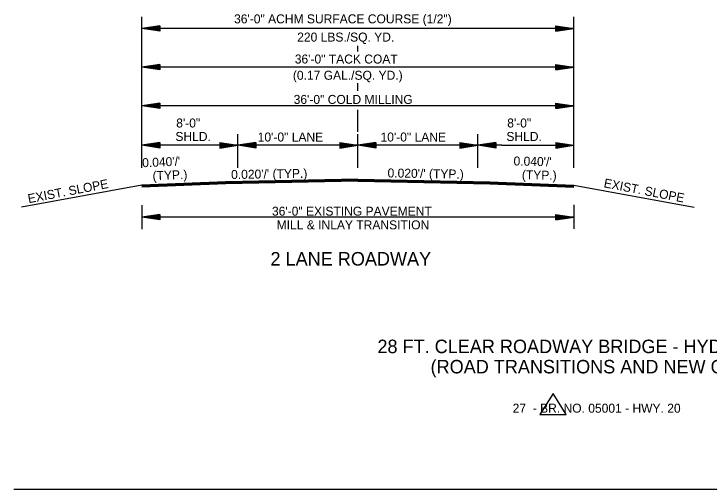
# Model space of a CAD drawing. Extents: x 544199 to 1930787, y -1968972 to 596640.
# Drawn here: x 546303 to 546882, y -1960808 to -1960412 of the extents above; entities that cross this region are included whole.
import ezdxf

# ---------------------------------------------------------------- set-up
doc = ezdxf.new("R2010")
doc.units = 0
doc.layers.add('R_Border', color=7, linetype='Continuous')
doc.layers.add('R_Draft', color=7, linetype='Continuous')

msp = doc.modelspace()

# ---------------------------------------------------------------- linework, layer by layer
at = {"layer": 'R_Border'}
for p, q in [((546479.58, -1960552.03), (546409.58, -1960554.83)), ((546479.58, -1960552.33), (546409.58, -1960555.13)), ((546479.58, -1960552.63), (546409.58, -1960555.43)), ((546479.58, -1960552.93), (546409.58, -1960555.73)), ((546479.58, -1960553.23), (546409.58, -1960556.03)), ((546479.58, -1960553.53), (546409.58, -1960556.33)), ((546479.58, -1960553.7), (546409.58, -1960556.5)), ((546699.58, -1960552.03), (546769.58, -1960554.83)), ((546699.58, -1960552.33), (546769.58, -1960555.13)), ((546699.58, -1960552.63), (546769.58, -1960555.43)), ((546699.58, -1960552.93), (546769.58, -1960555.73)), ((546699.58, -1960553.23), (546769.58, -1960556.03)), ((546699.58, -1960553.53), (546769.58, -1960556.33)), ((546699.58, -1960553.7), (546769.58, -1960556.5)), ((546752.16, -1960728.48), (546741.12, -1960745.79)), ((546763.21, -1960745.79), (546752.16, -1960728.48)), ((546741.12, -1960745.79), (546763.21, -1960745.79)), ((546303.14, -1960808.08), (547224.71, -1960808.08))]:
    msp.add_line(p, q, dxfattribs=at)
at = {"layer": 'R_Draft'}
for p, q in [((546409.58, -1960540.28), (546409.58, -1960414.32)), ((546769.58, -1960540.28), (546769.58, -1960414.32)), ((546424.58, -1960421.96), (546409.58, -1960424.21)), ((546424.58, -1960422.34), (546412.08, -1960424.21)), ((546424.58, -1960422.72), (546414.66, -1960424.21)), ((546424.58, -1960423.09), (546417.16, -1960424.21)), ((546424.58, -1960423.48), (546419.7, -1960424.21)), ((546424.58, -1960421.96), (546424.58, -1960426.46)), ((546754.58, -1960421.96), (546769.58, -1960424.21)), ((546754.58, -1960426.46), (546754.58, -1960421.96)), ((546754.58, -1960422.34), (546767.07, -1960424.21)), ((546754.58, -1960422.72), (546764.49, -1960424.21)), ((546754.58, -1960423.09), (546762, -1960424.21)), ((546754.58, -1960423.48), (546759.45, -1960424.21)), ((546769.58, -1960424.21), (546409.58, -1960424.21)), ((546424.58, -1960426.46), (546409.58, -1960424.21)), ((546424.58, -1960426.09), (546412.08, -1960424.21)), ((546424.58, -1960425.7), (546414.66, -1960424.21)), ((546424.58, -1960425.33), (546417.16, -1960424.21)), ((546424.58, -1960424.95), (546419.7, -1960424.21)), ((546424.58, -1960423.86), (546422.21, -1960424.21)), ((546424.58, -1960424.56), (546422.21, -1960424.21)), ((546754.58, -1960423.86), (546756.95, -1960424.21)), ((546754.58, -1960426.46), (546769.58, -1960424.21)), ((546754.58, -1960424.94), (546759.45, -1960424.21)), ((546754.58, -1960425.7), (546764.49, -1960424.21)), ((546754.58, -1960426.09), (546767.07, -1960424.21)), ((546754.58, -1960425.33), (546762, -1960424.21)), ((546754.58, -1960424.56), (546756.95, -1960424.21)), ((546589.58, -1960443.18), (546589.58, -1960438.56)), ((546424.58, -1960454.05), (546409.58, -1960456.3)), ((546769.58, -1960456.3), (546409.58, -1960456.3)), ((546424.58, -1960458.55), (546409.58, -1960456.3)), ((546424.58, -1960454.42), (546412.08, -1960456.3)), ((546424.58, -1960458.17), (546412.08, -1960456.3)), ((546424.58, -1960454.8), (546414.66, -1960456.3)), ((546424.58, -1960457.79), (546414.66, -1960456.3)), ((546424.58, -1960455.18), (546417.16, -1960456.3)), ((546424.58, -1960457.41), (546417.16, -1960456.3)), ((546424.58, -1960455.57), (546419.7, -1960456.3)), ((546424.58, -1960457.03), (546419.7, -1960456.3)), ((546424.58, -1960455.94), (546422.21, -1960456.3)), ((546424.58, -1960456.65), (546422.21, -1960456.3)), ((546424.58, -1960454.05), (546424.58, -1960458.55)), ((546754.58, -1960454.05), (546769.58, -1960456.3)), ((546754.58, -1960458.55), (546754.58, -1960454.05)), ((546754.58, -1960454.42), (546767.07, -1960456.3)), ((546754.58, -1960454.8), (546764.49, -1960456.3)), ((546754.58, -1960455.18), (546762, -1960456.3)), ((546754.58, -1960455.56), (546759.45, -1960456.3)), ((546754.58, -1960455.94), (546756.95, -1960456.3)), ((546754.58, -1960458.55), (546769.58, -1960456.3)), ((546754.58, -1960457.02), (546759.45, -1960456.3)), ((546754.58, -1960457.79), (546764.49, -1960456.3)), ((546754.58, -1960458.17), (546767.07, -1960456.3)), ((546754.58, -1960457.41), (546762, -1960456.3)), ((546754.58, -1960456.65), (546756.95, -1960456.3)), ((546589.58, -1960475.99), (546589.58, -1960469.83)), ((546424.58, -1960486.43), (546409.58, -1960488.68)), ((546424.58, -1960486.81), (546412.08, -1960488.68)), ((546424.58, -1960487.19), (546414.66, -1960488.68)), ((546424.58, -1960486.43), (546424.58, -1960490.93)), ((546754.58, -1960486.43), (546769.58, -1960488.68)), ((546754.58, -1960490.93), (546754.58, -1960486.43)), ((546754.58, -1960486.81), (546767.07, -1960488.68)), ((546754.58, -1960487.19), (546764.49, -1960488.68)), ((546769.58, -1960488.68), (546409.58, -1960488.68)), ((546424.58, -1960490.93), (546409.58, -1960488.68)), ((546424.58, -1960490.56), (546412.08, -1960488.68)), ((546424.58, -1960490.17), (546414.66, -1960488.68)), ((546424.58, -1960487.56), (546417.16, -1960488.68)), ((546424.58, -1960489.8), (546417.16, -1960488.68)), ((546424.58, -1960487.95), (546419.7, -1960488.68)), ((546424.58, -1960489.42), (546419.7, -1960488.68)), ((546424.58, -1960488.33), (546422.21, -1960488.68)), ((546424.58, -1960489.03), (546422.21, -1960488.68)), ((546589.58, -1960500.33), (546589.58, -1960492.06)), ((546754.58, -1960487.56), (546762, -1960488.68)), ((546754.58, -1960487.95), (546759.45, -1960488.68)), ((546754.58, -1960488.33), (546756.95, -1960488.68)), ((546754.58, -1960490.93), (546769.58, -1960488.68)), ((546754.58, -1960489.41), (546759.45, -1960488.68)), ((546754.58, -1960490.17), (546764.49, -1960488.68)), ((546754.58, -1960490.56), (546767.07, -1960488.68)), ((546754.58, -1960489.8), (546762, -1960488.68)), ((546754.58, -1960489.03), (546756.95, -1960488.68)), ((546589.58, -1960510.2), (546589.58, -1960500.33)), ((546489.58, -1960540.28), (546489.58, -1960512.33)), ((546589.58, -1960540.28), (546589.58, -1960512.33)), ((546689.58, -1960540.28), (546689.58, -1960512.33)), ((546424.58, -1960519.27), (546409.58, -1960521.52)), ((546469.58, -1960521.52), (546409.58, -1960521.52)), ((546424.58, -1960523.77), (546409.58, -1960521.52)), ((546424.58, -1960519.64), (546412.08, -1960521.52)), ((546424.58, -1960523.39), (546412.08, -1960521.52)), ((546424.58, -1960520.02), (546414.66, -1960521.52)), ((546424.58, -1960523.01), (546414.66, -1960521.52)), ((546424.58, -1960520.4), (546417.16, -1960521.52)), ((546424.58, -1960522.63), (546417.16, -1960521.52)), ((546424.58, -1960520.79), (546419.7, -1960521.52)), ((546424.58, -1960522.25), (546419.7, -1960521.52)), ((546424.58, -1960521.16), (546422.21, -1960521.52)), ((546424.58, -1960521.87), (546422.21, -1960521.52)), ((546424.58, -1960519.27), (546424.58, -1960523.77)), ((546589.58, -1960521.52), (546469.58, -1960521.52)), ((546474.58, -1960519.27), (546489.58, -1960521.52)), ((546474.58, -1960519.27), (546474.58, -1960523.77)), ((546474.58, -1960519.64), (546487.07, -1960521.52)), ((546474.58, -1960520.02), (546484.49, -1960521.52)), ((546474.58, -1960520.4), (546482, -1960521.52)), ((546474.58, -1960520.79), (546479.45, -1960521.52)), ((546474.58, -1960521.16), (546476.95, -1960521.52)), ((546474.58, -1960523.77), (546489.58, -1960521.52)), ((546474.58, -1960522.25), (546479.45, -1960521.52)), ((546474.58, -1960523.01), (546484.49, -1960521.52)), ((546474.58, -1960523.39), (546487.07, -1960521.52)), ((546474.58, -1960522.63), (546482, -1960521.52)), ((546474.58, -1960521.87), (546476.95, -1960521.52)), ((546504.58, -1960519.27), (546489.58, -1960521.52)), ((546504.58, -1960523.77), (546489.58, -1960521.52)), ((546504.58, -1960519.64), (546492.08, -1960521.52)), ((546504.58, -1960523.39), (546492.08, -1960521.52)), ((546504.58, -1960520.02), (546494.66, -1960521.52)), ((546504.58, -1960523.01), (546494.66, -1960521.52)), ((546504.58, -1960520.4), (546497.16, -1960521.52)), ((546504.58, -1960522.63), (546497.16, -1960521.52)), ((546504.58, -1960520.79), (546499.7, -1960521.52)), ((546504.58, -1960522.25), (546499.7, -1960521.52)), ((546504.58, -1960521.16), (546502.21, -1960521.52)), ((546504.58, -1960521.87), (546502.21, -1960521.52)), ((546504.58, -1960519.27), (546504.58, -1960523.77)), ((546574.58, -1960519.27), (546589.58, -1960521.52)), ((546574.58, -1960519.27), (546574.58, -1960523.77)), ((546574.58, -1960519.64), (546587.07, -1960521.52)), ((546574.58, -1960520.02), (546584.49, -1960521.52)), ((546574.58, -1960520.4), (546582, -1960521.52)), ((546574.58, -1960520.79), (546579.45, -1960521.52)), ((546574.58, -1960521.16), (546576.95, -1960521.52)), ((546574.58, -1960523.77), (546589.58, -1960521.52)), ((546574.58, -1960522.25), (546579.45, -1960521.52)), ((546574.58, -1960523.01), (546584.49, -1960521.52)), ((546574.58, -1960523.39), (546587.07, -1960521.52)), ((546574.58, -1960522.63), (546582, -1960521.52)), ((546574.58, -1960521.87), (546576.95, -1960521.52)), ((546604.58, -1960519.27), (546589.58, -1960521.52)), ((546709.58, -1960521.52), (546589.58, -1960521.52)), ((546604.58, -1960523.77), (546589.58, -1960521.52)), ((546604.58, -1960519.64), (546592.08, -1960521.52)), ((546604.58, -1960523.39), (546592.08, -1960521.52)), ((546604.58, -1960520.02), (546594.66, -1960521.52)), ((546604.58, -1960523.01), (546594.66, -1960521.52)), ((546604.58, -1960520.4), (546597.16, -1960521.52)), ((546604.58, -1960522.63), (546597.16, -1960521.52)), ((546604.58, -1960520.79), (546599.7, -1960521.52)), ((546604.58, -1960522.25), (546599.7, -1960521.52)), ((546604.58, -1960521.16), (546602.21, -1960521.52)), ((546604.58, -1960521.87), (546602.21, -1960521.52)), ((546604.58, -1960519.27), (546604.58, -1960523.77)), ((546674.58, -1960519.27), (546689.58, -1960521.52)), ((546674.58, -1960519.27), (546674.58, -1960523.77)), ((546674.58, -1960519.64), (546687.07, -1960521.52)), ((546674.58, -1960520.02), (546684.49, -1960521.52)), ((546674.58, -1960520.4), (546682, -1960521.52)), ((546674.58, -1960520.79), (546679.45, -1960521.52)), ((546674.58, -1960521.16), (546676.95, -1960521.52)), ((546674.58, -1960523.77), (546689.58, -1960521.52)), ((546674.58, -1960522.25), (546679.45, -1960521.52)), ((546674.58, -1960523.01), (546684.49, -1960521.52)), ((546674.58, -1960523.39), (546687.07, -1960521.52)), ((546674.58, -1960522.63), (546682, -1960521.52)), ((546674.58, -1960521.87), (546676.95, -1960521.52)), ((546704.58, -1960519.27), (546689.58, -1960521.52)), ((546704.58, -1960523.77), (546689.58, -1960521.52)), ((546704.58, -1960519.64), (546692.08, -1960521.52)), ((546704.58, -1960523.39), (546692.08, -1960521.52)), ((546704.58, -1960520.02), (546694.66, -1960521.52)), ((546704.58, -1960523.01), (546694.66, -1960521.52)), ((546704.58, -1960520.4), (546697.16, -1960521.52)), ((546704.58, -1960522.63), (546697.16, -1960521.52)), ((546704.58, -1960520.79), (546699.7, -1960521.52)), ((546704.58, -1960522.25), (546699.7, -1960521.52)), ((546704.58, -1960521.16), (546702.21, -1960521.52)), ((546704.58, -1960521.87), (546702.21, -1960521.52)), ((546704.58, -1960519.27), (546704.58, -1960523.77)), ((546709.58, -1960521.52), (546769.58, -1960521.52)), ((546754.58, -1960519.27), (546769.58, -1960521.52)), ((546754.58, -1960519.27), (546754.58, -1960523.77)), ((546754.58, -1960519.64), (546767.07, -1960521.52)), ((546754.58, -1960520.02), (546764.49, -1960521.52)), ((546754.58, -1960520.4), (546762, -1960521.52)), ((546754.58, -1960520.79), (546759.45, -1960521.52)), ((546754.58, -1960521.16), (546756.95, -1960521.52)), ((546754.58, -1960523.77), (546769.58, -1960521.52)), ((546754.58, -1960522.25), (546759.45, -1960521.52)), ((546754.58, -1960523.01), (546764.49, -1960521.52)), ((546754.58, -1960523.39), (546767.07, -1960521.52)), ((546754.58, -1960522.63), (546762, -1960521.52)), ((546754.58, -1960521.87), (546756.95, -1960521.52)), ((546589.58, -1960549.83), (546479.58, -1960552.03)), ((546589.58, -1960550.13), (546479.58, -1960552.33)), ((546589.58, -1960550.43), (546479.58, -1960552.63)), ((546589.58, -1960550.73), (546479.58, -1960552.93)), ((546589.58, -1960551.03), (546479.58, -1960553.23)), ((546589.58, -1960549.83), (546699.58, -1960552.03)), ((546589.58, -1960550.13), (546699.58, -1960552.33)), ((546589.58, -1960550.43), (546699.58, -1960552.63)), ((546589.58, -1960550.73), (546699.58, -1960552.93)), ((546589.58, -1960551.03), (546699.58, -1960553.23)), ((546409.58, -1960554.83), (546309.51, -1960573.2)), ((546589.58, -1960551.33), (546479.58, -1960553.53)), ((546589.58, -1960551.5), (546479.58, -1960553.7)), ((546589.58, -1960551.33), (546699.58, -1960553.53)), ((546589.58, -1960551.5), (546699.58, -1960553.7)), ((546769.58, -1960554.83), (546869.65, -1960573.2)), ((546409.58, -1960571.48), (546409.58, -1960591.48)), ((546769.58, -1960571.23), (546769.58, -1960591.23)), ((546424.58, -1960579.23), (546409.58, -1960581.48)), ((546424.58, -1960579.61), (546412.08, -1960581.48)), ((546424.58, -1960579.99), (546414.66, -1960581.48)), ((546424.58, -1960579.23), (546424.58, -1960583.73)), ((546754.58, -1960579.23), (546769.58, -1960581.48)), ((546754.58, -1960583.73), (546754.58, -1960579.23)), ((546754.58, -1960579.61), (546767.07, -1960581.48)), ((546754.58, -1960579.99), (546764.49, -1960581.48)), ((546424.58, -1960583.73), (546409.58, -1960581.48)), ((546769.58, -1960581.48), (546409.58, -1960581.48)), ((546424.58, -1960583.36), (546412.08, -1960581.48)), ((546424.58, -1960582.98), (546414.66, -1960581.48)), ((546424.58, -1960580.37), (546417.16, -1960581.48)), ((546424.58, -1960582.6), (546417.16, -1960581.48)), ((546424.58, -1960580.76), (546419.7, -1960581.48)), ((546424.58, -1960582.22), (546419.7, -1960581.48)), ((546424.58, -1960581.13), (546422.21, -1960581.48)), ((546424.58, -1960581.84), (546422.21, -1960581.48)), ((546754.58, -1960580.37), (546762, -1960581.48)), ((546754.58, -1960580.75), (546759.45, -1960581.48)), ((546754.58, -1960581.13), (546756.95, -1960581.48)), ((546754.58, -1960583.73), (546769.58, -1960581.48)), ((546754.58, -1960582.21), (546759.45, -1960581.48)), ((546754.58, -1960582.98), (546764.49, -1960581.48)), ((546754.58, -1960583.36), (546767.07, -1960581.48)), ((546754.58, -1960582.6), (546762, -1960581.48)), ((546754.58, -1960581.84), (546756.95, -1960581.48))]:
    msp.add_line(p, q, dxfattribs=at)

# ---------------------------------------------------------------- texts
for s, height, p in [('36\'-0" ACHM SURFACE COURSE (1/2")', 7.5, (546486.5, -1960419.86)), ('220 LBS./SQ. YD. ', 7.5, (546539.09, -1960435.04)), ('36\'-0" TACK COAT', 7.5, (546537.05, -1960453.33)), ('(0.17 GAL./SQ. YD.)', 7.5, (546535.49, -1960466.87)), ('36\'-0" COLD MILLING', 7.5, (546536.14, -1960487.01)), ('8\'-0"', 7.5, (546438.32, -1960506.65)), ('8\'-0"', 7.5, (546713.98, -1960506.65)), ('SHLD.', 7.5, (546437.64, -1960517.9)), ('SHLD.', 7.5, (546713.3, -1960517.9)), ('10\'-0" LANE', 7.5, (546506.18, -1960518.34)), ('10\'-0" LANE', 7.5, (546608.46, -1960518.34)), ('36\'-0" EXISTING PAVEMENT ', 7.5, (546518.07, -1960580.16)), ('MILL & INLAY TRANSITION', 7.5, (546521.97, -1960591.57)), ('2 LANE ROADWAY', 11.25, (546516.85, -1960621.71)), ('28 FT. CLEAR ROADWAY BRIDGE - HYDRODEMOLITION', 11.25, (546605.91, -1960694.76)), ('(ROAD TRANSITIONS AND NEW GUARDRAIL)', 11.25, (546650.16, -1960711.63)), ('      27  - BR. NO. 05001 - HWY. 20', 7.5, (546701.79, -1960744.38))]:
    msp.add_text(s, height=height, dxfattribs=at).set_placement(p)
for s, rotation, p in [("  0.040'/'", 2.44797, (546404.56, -1960540.05)), ("0.040'/'", 358.68162, (546719.18, -1960538.27)), (' (TYP.)', 2.44797, (546415.99, -1960550.82)), ("0.020'/' (TYP.)", 0.97192, (546484.1, -1960549.62)), ("0.020'/' (TYP.)", 359.02808, (546614.28, -1960548.25)), ('(TYP.)', 358.68162, (546726.12, -1960549.69)), ('EXIST. SLOPE', 10.88286, (546315.49, -1960569.82)), ('EXIST. SLOPE', 349.11714, (546793.96, -1960556.42))]:
    msp.add_text(s, height=7.5, rotation=rotation, dxfattribs=at).set_placement(p)

doc.saveas('drawing.dxf')
